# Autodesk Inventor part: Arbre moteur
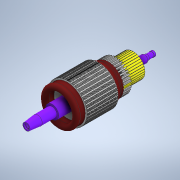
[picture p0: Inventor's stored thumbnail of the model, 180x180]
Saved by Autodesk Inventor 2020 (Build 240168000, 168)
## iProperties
Created: 2003-05
Part Number: Arbre moteur
Material: Générique
Document SubType Name: Modeling
Designer: Bruno
Density: 1 g/cm^3
Appearance: Par défaut
Author: Bruno
Sending System: SolidWorks 2011
Last Author: frederic
Last Saved: 2012-02-20
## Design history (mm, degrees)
feature "Répétition circulaire2"
node "Solide1"
